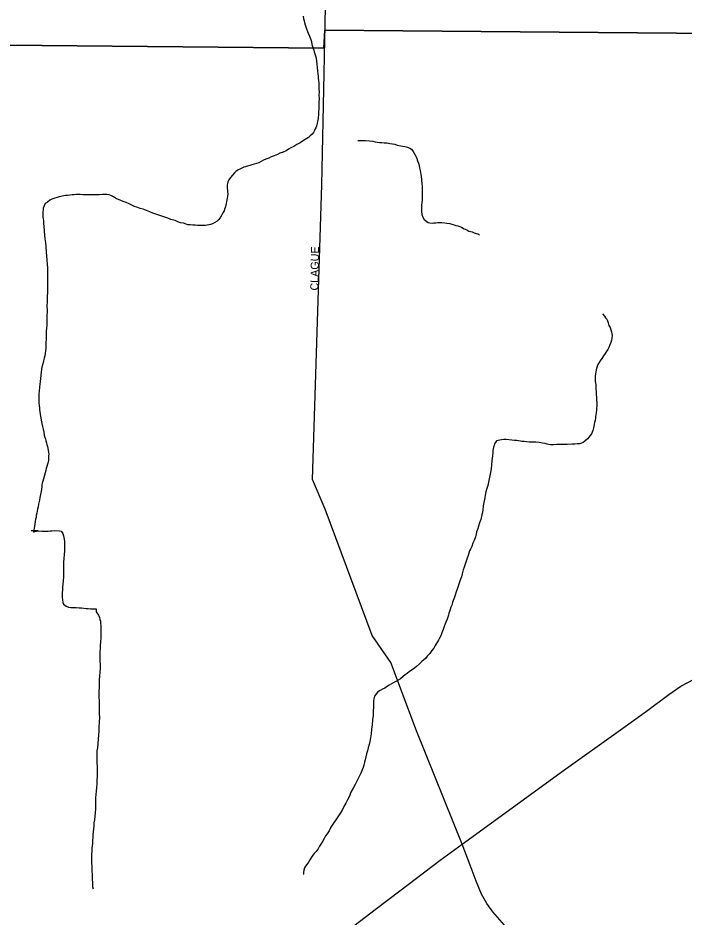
# Model space of a CAD drawing. Extents: x 2010165 to 2382125, y 1060529 to 1407316.
# Drawn here: x 2135691 to 2139850, y 1251239 to 1256857 of the extents above; entities that cross this region are included whole.
import ezdxf

# ---------------------------------------------------------------- set-up
doc = ezdxf.new("R2010")
doc.units = 0
for name, color, linetype in [('GM_X_City_Street', 7, 'Continuous'), ('GM_X_City_Street_Text', 7, 'Continuous'), ('GM_X_Corporation', 7, 'Continuous'), ('GM_X_Minor_River', 7, 'Continuous'), ('GM_X_State_Route', 7, 'Continuous')]:
    doc.layers.add(name, color=color, linetype=linetype)

msp = doc.modelspace()

# ---------------------------------------------------------------- linework, layer by layer
at = {"layer": 'GM_X_City_Street'}
for points in [[(2137605.5, 1256618.4), (2137620, 1257341.6), (2137697.2, 1259818.4), (2137746.2, 1261986.9), (2137847.1, 1265266.2)], [(2137603.5, 1256515.1), (2137605.4, 1256614.4), (2137605.5, 1256618.4)], [(2138464.5, 1251694.1), (2138180.8, 1252403.5), (2138019.9, 1252829.1), (2137902.1, 1252998.8), (2137609.2, 1253788.2), (2137531.1, 1253972.5), (2137589.4, 1255814.4), (2137603.4, 1256510.5), (2137603.5, 1256515.1)], [(2139262.6, 1248302.6), (2139246.4, 1248893.7), (2139229.9, 1249372.7), (2139237.4, 1250014), (2139239, 1250479), (2139238.9, 1250585.2), (2139106.7, 1250729.4), (2138951.7, 1250940.5), (2138858.6, 1251041.4), (2138757.8, 1251154.9), (2138656.8, 1251271.6), (2138619, 1251323.6), (2138585.9, 1251381.9), (2138552.8, 1251463.9), (2138515, 1251563.2), (2138464.5, 1251694.1)]]:
    msp.add_lwpolyline(points, dxfattribs=at)
at = {"layer": 'GM_X_Corporation'}
for points in [[(2140063.6, 1257468.8), (2140046.9, 1256760.6), (2137606.4, 1256780.5), (2137600.8, 1256668.1), (2134957.2, 1256693.9), (2134883.7, 1254009.9), (2132300.2, 1254032), (2132279.6, 1253153.3), (2132271.1, 1252778.2), (2132262.1, 1252535.5), (2132230.3, 1251466.2), (2124149.1, 1251538.9)], [(2124149.1, 1251538.9), (2132230.3, 1251466.2), (2132262.1, 1252535.5), (2132271.1, 1252778.2), (2132279.6, 1253153.3), (2132300.2, 1254032), (2134883.7, 1254009.9), (2134957.2, 1256693.9), (2137600.8, 1256668.1), (2137606.4, 1256780.5), (2140046.9, 1256760.6), (2139992.1, 1252819.5), (2139898.6, 1245676.5), (2139872.9, 1244267.3)]]:
    msp.add_lwpolyline(points, dxfattribs=at)
at = {"layer": 'GM_X_Minor_River'}
for points in [[(2137472.5, 1256869), (2137474.5, 1256854.9), (2137478.6, 1256838.9), (2137480.6, 1256828.9), (2137484.7, 1256814.8), (2137488.7, 1256802.8), (2137492.8, 1256788.8), (2137498.9, 1256772.7), (2137502.9, 1256762.7), (2137511, 1256744.7), (2137515.1, 1256732.7), (2137519.1, 1256722.6), (2137523.2, 1256710.6), (2137527.2, 1256692.6), (2137531.3, 1256678.5), (2137535.4, 1256666.5), (2137539.4, 1256656.5), (2137541.5, 1256646.4), (2137545.5, 1256634.4), (2137549.6, 1256620.4), (2137553.6, 1256606.3), (2137555.7, 1256588.3), (2137557.8, 1256568.2), (2137559.9, 1256548.2), (2137562, 1256524.1), (2137564, 1256508.1), (2137566.1, 1256494), (2137566.1, 1256482), (2137568.2, 1256465.9), (2137570.2, 1256447.9), (2137570.3, 1256429.8), (2137570.4, 1256413.8), (2137572.4, 1256395.7), (2137570.5, 1256375.6), (2137572.6, 1256353.6), (2137570.7, 1256331.5), (2137570.8, 1256305.4), (2137570.8, 1256287.3), (2137568.9, 1256273.3), (2137568.9, 1256259.2), (2137565, 1256229.1), (2137561, 1256211), (2137559.1, 1256199), (2137557.1, 1256188.9), (2137553.1, 1256174.9), (2137547.2, 1256164.8), (2137543.2, 1256154.8), (2137537.2, 1256142.7), (2137529.2, 1256130.7), (2137515.2, 1256120.6), (2137505.2, 1256110.5), (2137495.2, 1256104.5), (2137485.2, 1256098.4), (2137473.2, 1256092.4), (2137453.2, 1256078.2), (2137433.1, 1256066.1), (2137413.1, 1256054), (2137395.1, 1256046), (2137381.1, 1256037.9), (2137367, 1256027.8), (2137347, 1256019.7), (2137327, 1256011.6), (2137310.9, 1256003.6), (2137290.9, 1255995.5), (2137272.9, 1255989.4), (2137256.8, 1255981.3), (2137238.8, 1255975.2), (2137224.8, 1255969.2), (2137210.8, 1255961.1), (2137194.7, 1255953), (2137180.7, 1255948.9), (2137166.7, 1255942.9), (2137152.6, 1255938.8), (2137138.6, 1255934.8), (2137124.6, 1255930.7), (2137112.5, 1255926.7), (2137102.5, 1255924.6), (2137092.5, 1255920.6), (2137076.5, 1255912.5), (2137066.5, 1255908.4), (2137052.4, 1255898.4), (2137042.4, 1255890.3), (2137018.5, 1255860.1), (2137008.5, 1255846.1), (2137002.5, 1255834), (2137000.5, 1255824), (2136998.6, 1255813.9), (2136998.6, 1255803.9), (2136998.6, 1255791.8), (2136998.7, 1255781.8), (2136998.7, 1255771.8), (2137000.8, 1255757.7), (2136998.8, 1255743.7), (2136996.9, 1255731.6)], [(2137814.3, 1256091.4), (2137840.4, 1256091.5), (2137860.5, 1256091.6), (2137886.6, 1256089.6), (2137906.6, 1256087.7), (2137922.7, 1256083.8), (2137934.7, 1256081.8), (2137948.8, 1256079.8), (2137962.8, 1256079.9), (2137978.9, 1256077.9), (2137997, 1256078), (2138013, 1256074), (2138029.1, 1256072), (2138045.2, 1256068.1), (2138059.2, 1256062.1), (2138081.3, 1256058.2), (2138095.4, 1256056.2), (2138107.4, 1256054.2), (2138123.5, 1256050.3), (2138137.6, 1256044.3), (2138147.6, 1256038.3), (2138159.7, 1256022.3), (2138167.8, 1256008.3), (2138175.9, 1255994.2), (2138181.9, 1255980.2), (2138186, 1255964.2), (2138192.1, 1255950.1), (2138196.1, 1255936.1), (2138198.2, 1255920.1), (2138202.3, 1255904), (2138204.3, 1255892), (2138206.4, 1255879.9), (2138208.4, 1255869.9), (2138212.6, 1255821.8), (2138214.6, 1255803.7), (2138214.7, 1255785.7), (2138214.8, 1255765.6), (2138214.9, 1255743.5), (2138214.9, 1255721.4), (2138213, 1255701.4), (2138211, 1255689.3), (2138211.1, 1255679.3), (2138211.1, 1255669.2), (2138211.2, 1255657.2), (2138211.2, 1255647.2), (2138213.3, 1255629.1), (2138219.3, 1255613.1), (2138227.4, 1255599.1), (2138243.5, 1255585.1), (2138253.6, 1255579.1), (2138263.6, 1255577.1), (2138277.7, 1255575.1), (2138287.7, 1255577.2), (2138299.7, 1255577.2), (2138311.8, 1255579.3), (2138325.8, 1255579.3), (2138337.8, 1255579.3), (2138355.9, 1255577.4), (2138370, 1255575.4), (2138388, 1255573.5), (2138400.1, 1255569.5), (2138414.2, 1255565.5), (2138426.2, 1255561.6), (2138438.3, 1255557.6), (2138450.3, 1255553.6), (2138460.4, 1255549.6), (2138476.5, 1255539.6), (2138494.5, 1255533.7), (2138506.6, 1255525.7), (2138526.7, 1255521.8), (2138540.8, 1255515.8), (2138552.8, 1255509.8), (2138562.9, 1255507.8), (2138566.9, 1255505.8), (2138572.9, 1255501.8)], [(2136996.9, 1255731.6), (2136994.9, 1255721.6), (2136992.9, 1255709.6), (2136991, 1255697.5), (2136989, 1255687.5), (2136987, 1255677.4), (2136981, 1255663.3), (2136979.1, 1255651.3), (2136971.1, 1255639.2), (2136965.1, 1255627.2), (2136955.1, 1255613.1), (2136945.1, 1255599), (2136935.2, 1255586.9), (2136921.1, 1255578.9), (2136905.1, 1255570.8), (2136893.1, 1255566.7), (2136883.1, 1255564.7), (2136863, 1255560.6), (2136844.9, 1255560.6), (2136830.9, 1255560.5), (2136812.8, 1255560.5), (2136796.8, 1255562.4), (2136782.7, 1255562.4), (2136766.7, 1255564.3), (2136752.6, 1255564.3), (2136740.6, 1255568.3), (2136724.5, 1255574.2), (2136706.4, 1255578.2), (2136690.4, 1255584.2), (2136672.3, 1255592.1), (2136646.1, 1255598.1), (2136626.1, 1255606), (2136608, 1255612), (2136589.9, 1255618), (2136533.6, 1255637.8), (2136515.5, 1255645.8), (2136493.4, 1255653.8), (2136473.4, 1255661.7), (2136453.3, 1255667.7), (2136433.2, 1255675.7), (2136419.1, 1255679.6), (2136403, 1255687.6), (2136384.9, 1255695.6), (2136366.9, 1255703.6), (2136348.8, 1255711.5), (2136332.7, 1255717.5), (2136318.6, 1255723.5), (2136306.6, 1255727.4), (2136288.5, 1255739.4), (2136270.4, 1255747.4), (2136260.3, 1255751.4), (2136246.3, 1255755.3), (2136234.2, 1255755.3), (2136218.2, 1255755.3), (2136198.1, 1255753.2), (2136176, 1255753.1), (2136158, 1255753.1), (2136143.9, 1255753), (2136129.9, 1255753), (2136111.8, 1255752.9), (2136095.8, 1255752.9), (2136079.7, 1255754.8), (2136063.7, 1255754.8), (2136051.6, 1255754.7), (2136041.6, 1255752.7), (2136029.6, 1255752.6), (2136015.5, 1255750.6), (2136001.5, 1255748.5), (2135987.4, 1255748.5), (2135977.4, 1255746.5), (2135949.3, 1255740.3), (2135935.3, 1255736.3), (2135921.3, 1255732.2), (2135903.2, 1255726.2), (2135891.2, 1255718.1), (2135875.2, 1255706), (2135861.2, 1255697.9), (2135849.2, 1255669.8), (2135847.4, 1255635.7), (2135847.4, 1255613.6), (2135849.5, 1255601.6), (2135851.5, 1255589.5), (2135851.6, 1255573.5), (2135853.7, 1255553.4), (2135855.8, 1255527.3), (2135857.9, 1255501.2), (2135860, 1255477.2), (2135864.1, 1255453.1), (2135866.2, 1255429), (2135868.3, 1255394.9), (2135870.4, 1255370.8), (2135872.5, 1255344.8), (2135872.6, 1255318.7), (2135874.7, 1255296.6), (2135874.7, 1255274.5), (2135874.8, 1255252.5), (2135874.9, 1255228.4), (2135875, 1255208.3), (2135875, 1255188.2), (2135875.1, 1255168.2), (2135875.2, 1255142.1)], [(2135875.2, 1255142.1), (2135873.3, 1255120), (2135873.3, 1255099.9), (2135873.4, 1255081.9), (2135871.5, 1255059.8), (2135873.6, 1255025.7), (2135871.7, 1254991.6), (2135871.8, 1254961.5), (2135871.9, 1254937.4), (2135870, 1254917.3), (2135868, 1254903.2), (2135868.1, 1254889.2), (2135868.1, 1254869.1), (2135868.2, 1254851.1), (2135866.3, 1254829), (2135864.3, 1254810.9), (2135864.4, 1254792.9), (2135858.5, 1254746.7), (2135854.6, 1254730.6), (2135850.6, 1254714.6), (2135846.7, 1254696.5), (2135840.7, 1254676.4), (2135838.8, 1254660.3), (2135836.8, 1254644.3), (2135831, 1254604.1), (2135829, 1254586), (2135827.1, 1254568), (2135825.1, 1254551.9), (2135823.2, 1254523.8), (2135821.3, 1254509.8), (2135821.3, 1254493.7), (2135821.4, 1254471.6), (2135821.5, 1254451.6), (2135823.5, 1254435.5), (2135825.6, 1254421.5), (2135825.6, 1254409.4), (2135827.7, 1254397.4), (2135829.7, 1254379.3), (2135833.8, 1254359.3), (2135835.9, 1254345.2), (2135840, 1254323.2), (2135844, 1254305.1), (2135848.1, 1254287.1), (2135852.2, 1254269), (2135854.3, 1254251), (2135858.3, 1254236.9), (2135862.4, 1254226.9), (2135864.4, 1254214.9), (2135868.5, 1254202.9), (2135872.5, 1254190.8), (2135876.6, 1254178.8), (2135878.6, 1254168.8), (2135880.7, 1254154.7), (2135882.7, 1254144.7), (2135884.8, 1254132.7), (2135882.8, 1254120.6), (2135882.9, 1254108.6), (2135880.9, 1254094.5), (2135879, 1254082.5), (2135875, 1254068.4), (2135871, 1254054.4), (2135867.1, 1254042.3), (2135865.1, 1254030.2), (2135851.2, 1253978), (2135847.3, 1253962), (2135843.3, 1253949.9), (2135841.3, 1253937.9), (2135839.4, 1253927.8), (2135837.4, 1253913.8), (2135835.5, 1253897.7), (2135831.5, 1253879.6), (2135827.6, 1253861.6), (2135825.6, 1253843.5), (2135819.7, 1253819.4), (2135817.7, 1253803.3), (2135813.8, 1253787.3), (2135811.8, 1253775.2), (2135809.9, 1253763.2), (2135805.9, 1253749.1), (2135803.9, 1253735.1), (2135800, 1253725), (2135798, 1253710.9), (2135796, 1253696.9), (2135794.1, 1253682.8), (2135792.1, 1253668.8), (2135790.2, 1253656.7), (2135788.2, 1253646.7), (2135786.2, 1253646.7), (2135788.2, 1253646.7)], [(2139341.2, 1255008.6), (2139353.3, 1254994.6), (2139359.3, 1254984.5), (2139367.4, 1254974.5), (2139371.5, 1254964.5), (2139377.5, 1254952.5), (2139381.6, 1254936.4), (2139389.7, 1254922.4), (2139393.7, 1254908.4), (2139397.8, 1254896.4), (2139399.8, 1254884.3), (2139401.9, 1254872.3), (2139399.9, 1254856.2), (2139398, 1254844.2), (2139394, 1254830.1), (2139388, 1254814.1), (2139380.1, 1254798), (2139374.1, 1254785.9), (2139364.1, 1254771.8), (2139358.1, 1254761.8), (2139348.2, 1254745.7), (2139336.2, 1254729.6), (2139326.2, 1254715.5), (2139316.2, 1254697.4), (2139310.2, 1254687.4), (2139306.3, 1254673.3), (2139302.3, 1254659.2), (2139300.3, 1254647.2), (2139298.4, 1254633.1), (2139296.4, 1254619.1), (2139294.5, 1254607), (2139294.5, 1254597), (2139294.5, 1254587), (2139296.6, 1254576.9), (2139298.6, 1254564.9), (2139298.7, 1254552.9), (2139298.7, 1254540.8), (2139300.8, 1254518.8), (2139300.9, 1254502.7), (2139302.9, 1254490.7), (2139302.9, 1254478.6), (2139303, 1254466.6), (2139305, 1254456.6), (2139305.1, 1254444.5), (2139303.2, 1254406.4), (2139301.2, 1254392.3), (2139299.3, 1254376.3), (2139297.3, 1254366.2), (2139297.4, 1254356.2), (2139295.4, 1254344.1), (2139291.4, 1254330.1), (2139289.5, 1254318), (2139287.5, 1254306), (2139285.5, 1254296), (2139281.6, 1254279.9), (2139277.6, 1254269.8), (2139271.6, 1254259.8), (2139263.6, 1254247.7), (2139255.6, 1254237.7), (2139247.6, 1254227.6), (2139231.6, 1254213.5), (2139219.6, 1254205.4), (2139209.6, 1254201.4), (2139197.6, 1254197.3), (2139183.6, 1254195.3), (2139167.5, 1254195.2), (2139149.4, 1254195.2), (2139121.4, 1254193.1), (2139097.3, 1254193), (2139073.2, 1254192.9), (2139055.1, 1254192.9), (2139035.1, 1254190.8), (2139017, 1254190.8), (2139005, 1254192.7), (2138994.9, 1254194.7), (2138982.9, 1254198.7), (2138966.8, 1254200.6), (2138946.7, 1254204.6), (2138924.6, 1254206.5), (2138902.6, 1254206.4), (2138882.5, 1254206.4), (2138866.5, 1254208.3), (2138852.4, 1254210.3), (2138838.3, 1254210.2), (2138828.3, 1254212.2), (2138816.3, 1254214.2), (2138806.2, 1254216.2), (2138790.2, 1254218.1), (2138774.1, 1254220.1), (2138740, 1254224), (2138723.9, 1254223.9), (2138709.9, 1254221.9), (2138699.9, 1254219.8), (2138689.8, 1254217.8), (2138679.8, 1254215.8), (2138667.8, 1254195.7), (2138663.9, 1254185.6), (2138659.9, 1254175.6), (2138657.9, 1254165.5), (2138655.9, 1254155.5), (2138656, 1254141.4)], [(2138656, 1254141.4), (2138654.1, 1254121.4), (2138650.1, 1254091.2), (2138648.2, 1254065.1), (2138646.3, 1254039.1), (2138642.4, 1254017), (2138638.4, 1253996.9), (2138634.5, 1253976.8), (2138628.6, 1253956.7), (2138624.6, 1253936.6), (2138618.7, 1253916.6), (2138612.7, 1253896.5), (2138608.8, 1253876.4), (2138606.8, 1253858.3), (2138600.9, 1253830.2), (2138597, 1253808.1), (2138593.1, 1253780), (2138587.1, 1253751.9), (2138581.2, 1253723.8), (2138573.3, 1253701.7), (2138567.3, 1253681.6), (2138561.4, 1253661.5), (2138555.4, 1253645.4), (2138551.4, 1253631.4), (2138547.5, 1253615.3), (2138539.5, 1253593.2), (2138531.6, 1253575.1), (2138525.6, 1253555), (2138517.7, 1253538.9), (2138511.7, 1253526.9), (2138505.7, 1253512.8), (2138501.8, 1253498.7), (2138495.8, 1253482.7), (2138477.9, 1253426.4), (2138472, 1253408.3), (2138466, 1253384.2), (2138460.1, 1253366.2), (2138454.1, 1253350.1), (2138448.2, 1253332), (2138442.2, 1253313.9), (2138436.3, 1253293.8), (2138428.3, 1253271.7), (2138420.4, 1253251.6), (2138414.4, 1253231.6), (2138408.4, 1253217.5), (2138404.5, 1253205.4), (2138400.5, 1253187.4), (2138394.5, 1253175.3), (2138390.6, 1253161.2), (2138386.6, 1253149.2), (2138382.6, 1253139.1), (2138378.7, 1253125.1), (2138374.7, 1253113), (2138370.7, 1253101), (2138362.8, 1253082.9), (2138358.8, 1253070.8), (2138352.8, 1253054.8), (2138346.9, 1253036.7), (2138340.9, 1253020.6), (2138334.9, 1253008.5), (2138331, 1252996.5), (2138323, 1252982.4), (2138317, 1252970.3), (2138311, 1252958.3), (2138303, 1252946.2), (2138297.1, 1252936.2), (2138287.1, 1252920.1), (2138275.1, 1252904), (2138263.1, 1252885.9), (2138247.1, 1252869.8), (2138235.1, 1252855.7), (2138213.1, 1252835.6), (2138199.1, 1252821.5), (2138179.1, 1252805.3), (2138159.1, 1252787.2), (2138137.1, 1252773.1), (2138121.1, 1252761), (2138109.1, 1252752.9), (2138097.1, 1252742.9), (2138079.1, 1252728.8), (2138065.1, 1252718.7), (2138023, 1252696.5), (2138009, 1252688.4), (2137997, 1252680.3), (2137983, 1252670.3), (2137966.9, 1252662.2), (2137952.9, 1252654.1), (2137936.9, 1252644), (2137924.9, 1252629.9), (2137916.9, 1252619.9), (2137913, 1252601.8), (2137911, 1252589.8), (2137911.1, 1252571.7), (2137911.1, 1252553.6), (2137909.2, 1252525.5), (2137909.3, 1252499.4), (2137905.4, 1252471.3), (2137903.5, 1252441.2), (2137899.6, 1252413.1), (2137895.7, 1252385), (2137891.8, 1252358.9)], [(2135786.2, 1253646.7), (2135818.3, 1253652.8), (2135774.1, 1253654.7), (2135818.3, 1253652.8), (2135840.4, 1253650.9), (2135856.4, 1253650.9), (2135868.4, 1253651), (2135880.5, 1253651), (2135892.5, 1253653.1), (2135902.6, 1253653.1), (2135916.6, 1253655.1), (2135950.7, 1253653.2), (2135960.7, 1253651.3), (2135970.8, 1253635.2), (2135974.9, 1253621.2), (2135979, 1253601.1), (2135981.1, 1253585.1), (2135981.1, 1253569), (2135981.3, 1253526.9), (2135979.3, 1253504.8), (2135977.4, 1253480.7), (2135975.5, 1253456.6), (2135975.6, 1253434.6), (2135975.6, 1253416.5), (2135975.7, 1253400.4), (2135975.8, 1253380.4), (2135975.8, 1253362.3), (2135973.9, 1253342.2), (2135972, 1253320.2), (2135970, 1253300.1), (2135970.1, 1253282), (2135968.1, 1253268), (2135968.2, 1253257.9), (2135968.2, 1253247.9), (2135968.2, 1253237.9), (2135970.3, 1253221.8), (2135972.4, 1253205.8), (2135976.4, 1253193.7), (2135992.5, 1253181.8), (2136006.6, 1253175.8), (2136020.6, 1253173.8), (2136034.7, 1253173.8), (2136054.8, 1253173.9), (2136072.8, 1253172), (2136088.9, 1253172), (2136102.9, 1253170.1), (2136117, 1253168.1), (2136129, 1253168.1), (2136145.1, 1253166.2), (2136157.1, 1253166.2), (2136179.2, 1253164.3), (2136179.3, 1253146.2), (2136193.4, 1253126.2), (2136199.5, 1253110.2), (2136203.5, 1253098.1), (2136205.6, 1253088.1), (2136207.6, 1253076.1), (2136209.7, 1253058), (2136209.7, 1253041.9), (2136207.8, 1253021.9), (2136207.9, 1253003.8), (2136207.9, 1252983.8), (2136206, 1252959.6), (2136204.1, 1252935.6), (2136204.2, 1252917.5), (2136202.2, 1252897.4), (2136202.3, 1252877.4), (2136202.4, 1252859.3), (2136202.4, 1252839.2), (2136204.5, 1252817.2), (2136204.6, 1252793.1), (2136202.7, 1252769), (2136200.8, 1252744.9), (2136198.8, 1252720.8), (2136198.9, 1252694.7), (2136199, 1252672.6), (2136197.1, 1252650.6), (2136197.2, 1252630.5), (2136197.2, 1252610.4), (2136197.3, 1252592.4), (2136197.4, 1252574.3), (2136197.4, 1252552.2), (2136197.5, 1252530.2), (2136197.6, 1252510.1), (2136199.7, 1252486), (2136197.8, 1252459.9), (2136195.9, 1252425.8), (2136196, 1252399.7), (2136194.1, 1252377.6), (2136192.1, 1252351.5), (2136190.2, 1252323.4), (2136188.3, 1252297.3), (2136184.4, 1252277.2), (2136184.4, 1252259.2), (2136184.5, 1252243.1), (2136184.6, 1252223.1), (2136184.8, 1252158.8), (2136184.9, 1252138.8), (2136184.9, 1252116.7), (2136183, 1252094.6), (2136183.1, 1252070.5)], [(2137891.8, 1252358.9), (2137887.8, 1252336.8), (2137883.9, 1252316.7), (2137877.9, 1252296.6), (2137874, 1252278.6), (2137868, 1252258.5), (2137864.1, 1252240.4), (2137860.1, 1252222.3), (2137854.2, 1252206.3), (2137850.2, 1252188.2), (2137846.3, 1252174.1), (2137840.3, 1252158.1), (2137832.3, 1252138), (2137820.4, 1252113.8), (2137808.4, 1252091.7), (2137796.5, 1252067.6), (2137784.5, 1252045.5), (2137770.6, 1252019.4), (2137760.6, 1251995.2), (2137748.7, 1251971.1), (2137738.7, 1251951), (2137726.7, 1251930.9), (2137716.8, 1251910.8), (2137704.8, 1251890.7), (2137688.8, 1251864.6), (2137644.9, 1251800.2), (2137635, 1251778.1), (2137621, 1251760), (2137611, 1251745.9), (2137603, 1251729.8), (2137593.1, 1251711.7), (2137583.1, 1251695.6), (2137575.1, 1251681.6), (2137565.1, 1251665.5), (2137553.2, 1251649.4), (2137541.2, 1251635.3), (2137533.2, 1251625.2), (2137525.2, 1251613.2), (2137513.2, 1251597.1), (2137505.2, 1251583), (2137495.3, 1251566.9), (2137487.3, 1251556.9), (2137481.3, 1251546.8), (2137475.3, 1251532.8), (2137473.4, 1251516.7), (2137473.4, 1251506.7), (2137471.4, 1251506.6), (2137473.4, 1251506.7)], [(2136183.1, 1252070.5), (2136181.2, 1252048.4), (2136179.2, 1252026.4), (2136177.3, 1252004.3), (2136175.4, 1251984.2), (2136175.5, 1251964.1), (2136175.5, 1251940.1), (2136175.6, 1251914), (2136173.7, 1251891.9), (2136171.8, 1251869.8), (2136169.8, 1251847.7), (2136165.9, 1251827.6), (2136164, 1251809.6), (2136162, 1251789.5), (2136160.1, 1251771.4), (2136158.1, 1251753.4), (2136158.2, 1251735.3), (2136156.3, 1251719.2), (2136156.3, 1251699.2), (2136154.4, 1251685.1), (2136152.4, 1251669.1), (2136152.5, 1251651), (2136150.5, 1251632.9), (2136150.6, 1251616.9), (2136150.7, 1251600.8), (2136150.7, 1251584.8), (2136150.8, 1251572.7), (2136152.8, 1251560.7), (2136152.8, 1251550.6), (2136152.9, 1251538.6), (2136152.9, 1251522.6), (2136155, 1251508.5), (2136155, 1251496.5), (2136155.1, 1251482.4), (2136155.1, 1251470.4), (2136157.2, 1251458.3), (2136157.2, 1251448.3), (2136157.3, 1251434.3), (2136157.3, 1251430.2), (2136161.3, 1251416.2)]]:
    msp.add_lwpolyline(points, dxfattribs=at)
at = {"layer": 'GM_X_State_Route'}
msp.add_lwpolyline([(2137752.7, 1251156.5), (2137930.9, 1251293.6), (2138075.1, 1251404), (2138327.4, 1251594.7), (2138464.5, 1251694.1), (2139098.3, 1252156), (2139453, 1252409.8), (2139616.9, 1252526.5), (2139755.7, 1252628.9), (2139829.8, 1252681), (2139913.3, 1252726.7)], dxfattribs=at)

# ---------------------------------------------------------------- texts
at = {"layer": 'GM_X_City_Street_Text'}
msp.add_text('CLAGUE', height=50, rotation=88.9775, dxfattribs=at).set_placement((2137566.5, 1255154.1))

doc.saveas('drawing.dxf')
